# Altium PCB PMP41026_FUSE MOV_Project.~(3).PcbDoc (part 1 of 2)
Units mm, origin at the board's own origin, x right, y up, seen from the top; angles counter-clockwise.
Board outline 26.25 x 35 mm, 2 copper layers (Top Layer, Bottom Layer), stack 1.575 mm thick; 11 components, 9 nets, 22 pads, 48 vias.
Unrouted connection lines stored in the file: 16.
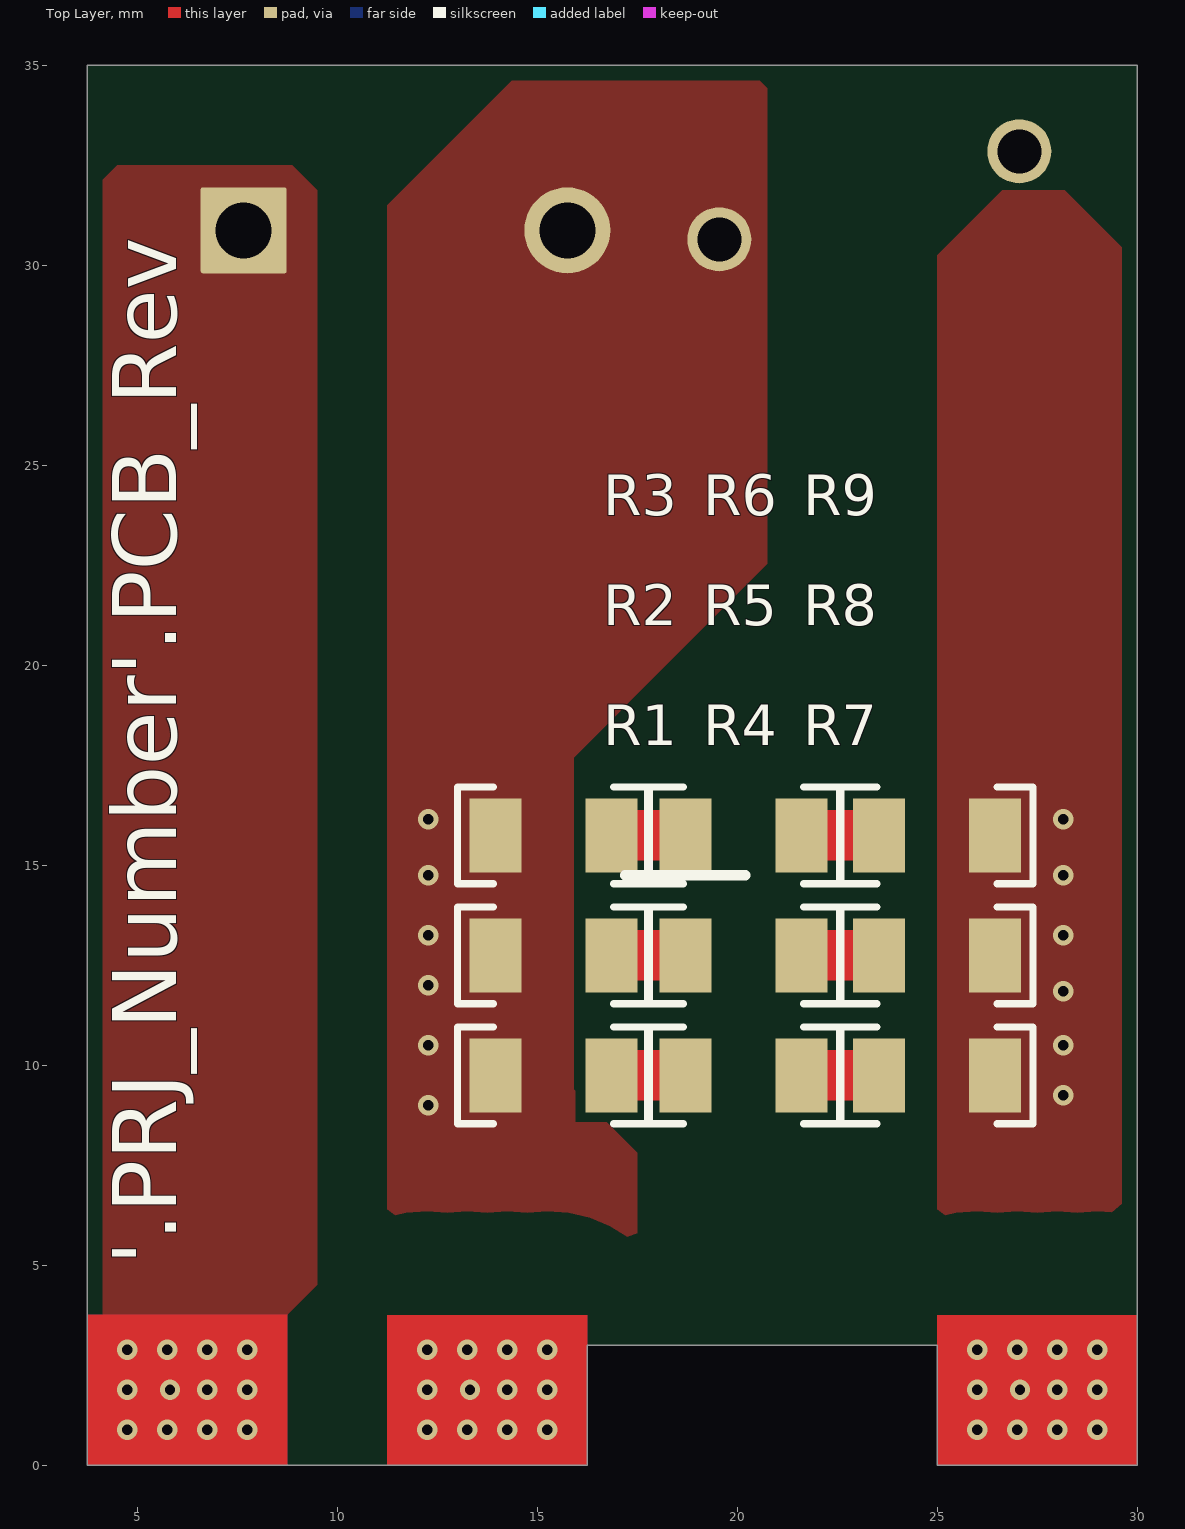
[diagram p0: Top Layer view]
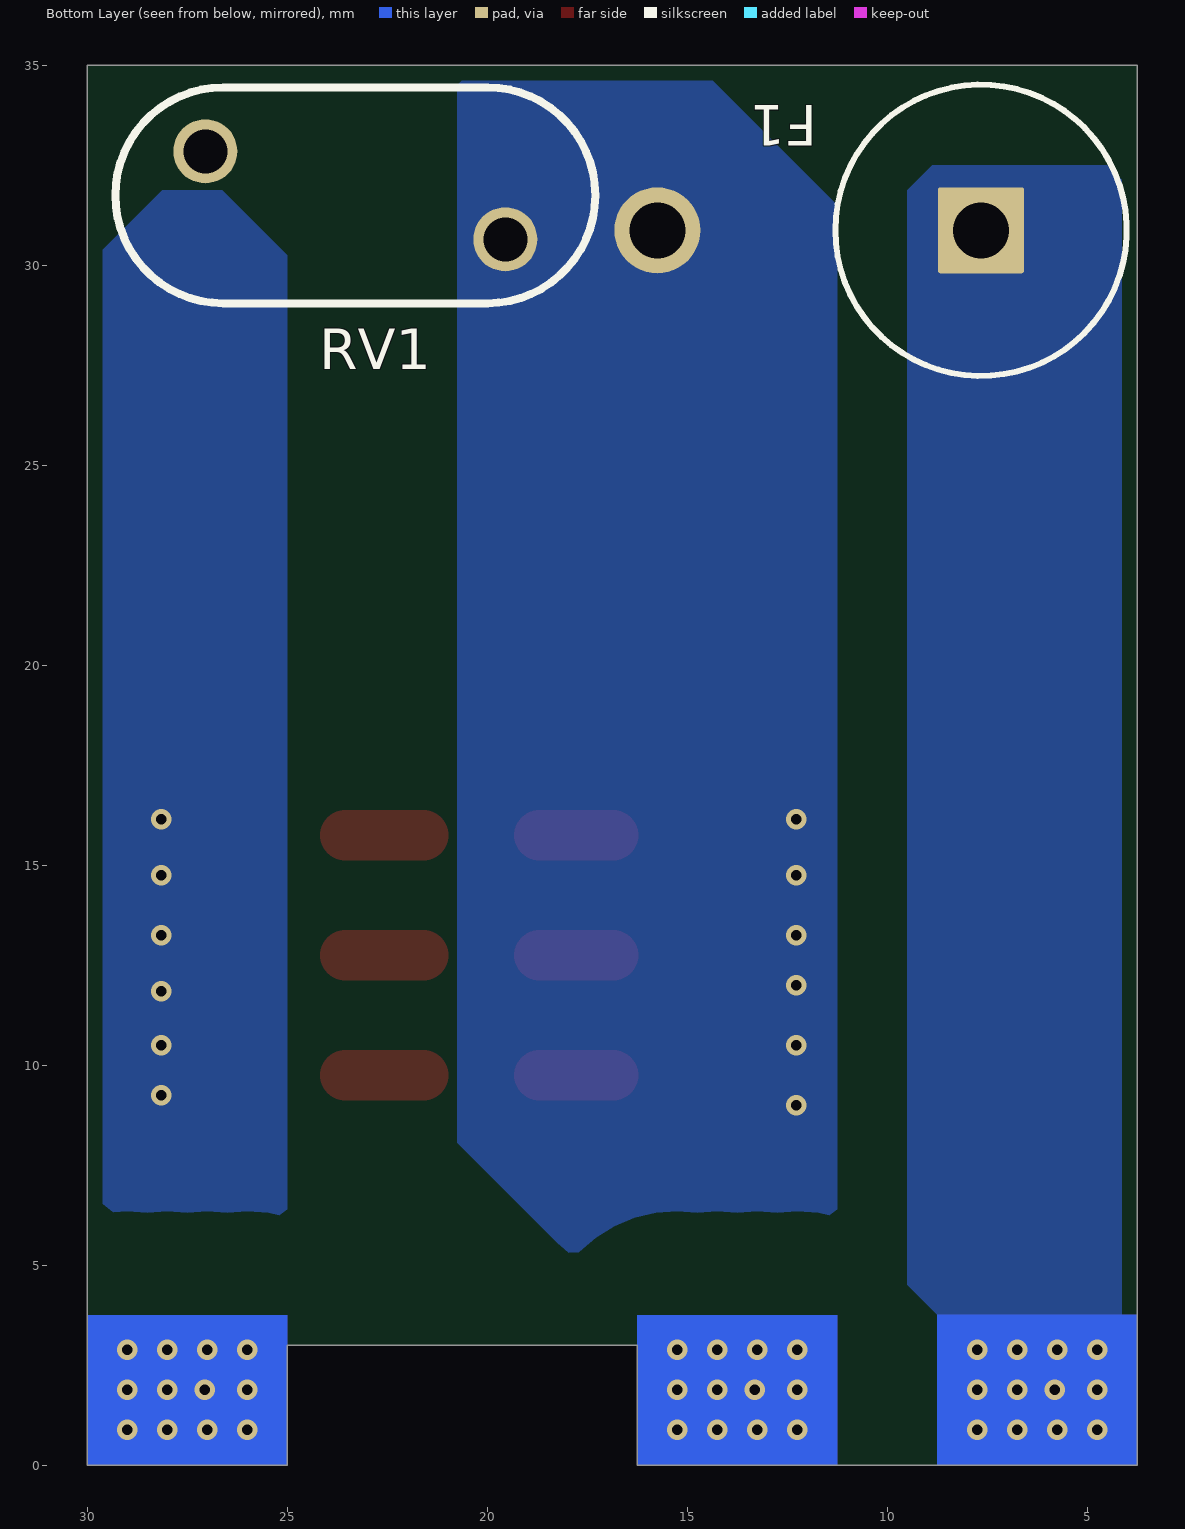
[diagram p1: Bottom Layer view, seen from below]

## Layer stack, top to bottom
Top Solder: solder mask 0.0102, Solder Resist, Dk 3.5
Top Layer: signal copper 0.0356
Dielectric1: core 1.5037, FR-4 High Tg, Dk 4.8
Bottom Layer: signal copper 0.0356
Bottom Solder: solder mask 0.0102, Solder Resist, Dk 3.5

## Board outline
3.75,0 3.75,35 30,35 30,0 25,0 25,3 16.25,3 16.25,0 11.25,0 8.75,0

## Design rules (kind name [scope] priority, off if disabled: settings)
AcuteAngle [All] p1: minimum=4.50000000000000E+0001 checktracksonly=FALSE
AssemblyTestPointUsage [All] p1: valid=2
BoardOutlineClearance BoardOutlineClearance_MountingHoles [OnCopper and InComponentClass('Mounting Holes')] p1: gap=1.016 ignorepadtopadclearanceinfootprint=FALSE
BoardOutlineClearance BoardOutlineClearance_Poly [OnCopper and IsPoly] p2: gap=0.381 ignorepadtopadclearanceinfootprint=FALSE
BoardOutlineClearance [OnCopper and Not InComponentClass('Logo') and not InComponentClass('FiducialMark') and not InRegion(1000,500,4000,800) and not InPoly] p3: gap=0.203 ignorepadtopadclearanceinfootprint=FALSE
Clearance Clearance_3 [InNetClass('L') vs Not InNetClass('L')] p1: gap=0.254 ignorepadtopadclearanceinfootprint=FALSE except(0: Arc-Hole Track-Hole SMDPad-Hole THPad-Hole Via-Hole Fill-Hole Poly-Hole Region-Hole Text-Hole)
Clearance Clearance_2 [InNetClass('N') vs InNetClass('L')] p2: gap=3.2 ignorepadtopadclearanceinfootprint=FALSE
Clearance Clearance_1 [InNetClass('N') vs Not InNetClass('N')] p3: gap=1.016 ignorepadtopadclearanceinfootprint=TRUE
Clearance Clearance_Keepouts [((IsTrack Or IsArc) And Not InPoly) And IsFree and IsKeepOut vs ((IsTrack Or IsArc) And Not InPoly) And IsFree and IsKeepOut] p4: gap=0 ignorepadtopadclearanceinfootprint=FALSE
Clearance Clearance_Poly [InPolygon] p5: gap=0.05 ignorepadtopadclearanceinfootprint=FALSE
Clearance Clearance_FiducialMark [IsKeepOut and InComponentClass('FiducialMark') vs IsPad and InComponentClass('FiducialMark')] p6: gap=0 ignorepadtopadclearanceinfootprint=FALSE
Clearance [All] p7: gap=0.05 ignorepadtopadclearanceinfootprint=TRUE
ComponentClearance ComponentClearance_MountingHoles_FiducialMarks [InComponentClass('Mounting Holes') vs InComponentClass('FiducialMark')] p1: gap=1.27 collisioncheckmode=3 verticalgap=0.254 showdistances=FALSE
ComponentClearance ComponentClearance_Shunt [InComponentClass('Header') vs InComponentClass('Shunt')] p2: gap=0 collisioncheckmode=3 verticalgap=0 showdistances=FALSE
ComponentClearance ComponentClearance_Logo [InComponentClass('Logo')] p3: gap=0.254 collisioncheckmode=3 verticalgap=0.254 showdistances=FALSE
ComponentClearance ComponentClearance_ScrewToNut [(HasFootprint('NY PMS 440 0025 PH')) vs (HasFootprint('Keystone_1902C'))] p4: gap=0.127 collisioncheckmode=3 verticalgap=0.254 showdistances=FALSE
ComponentClearance ComponentClearance_MountingHoles [InComponentClass('Mounting Holes')] p5: gap=1.27 collisioncheckmode=3 verticalgap=2540 showdistances=FALSE
ComponentClearance ComponentClearance_SmallPassives [HasFootprint('0201*') or HasFootprint('0402*') or HasFootprint('0508') or HasFootprint('0603*') or HasFootprint('0612') or HasFootprint('0805*') or HasFootprint('0815*') or HasFootprint('0830*') or HasFootprint('1206*') or HasFootprint('1210*') or HasFootprint('1808*') or HasFootprint('1812*') or HasFootprint('1825*') or HasFootprint('2010*') or HasFootprint('2220*') or HasFootprint('2225*') or HasFootprint('2512*') or HasFootprint('2728*') or HasFootprint('3518*') vs HasFootprint('0201*') or HasFootprint('0402*') or HasFootprint('0508') or HasFootprint('0603*') or HasFootprint('0612') or HasFootprint('0805*') or HasFootprint('0815*') or HasFootprint('0830*') or HasFootprint('1206*') or HasFootprint('1210*') or HasFootprint('1808*') or HasFootprint('1812*') or HasFootprint('1825*') or HasFootprint('2010*') or HasFootprint('2220*') or HasFootprint('2225*') or HasFootprint('2512*') or HasFootprint('2728*') or HasFootprint('3518*')] p6: gap=0.38 collisioncheckmode=3 verticalgap=0.254 showdistances=FALSE
ComponentClearance ComponentClearance_THtoSMT [IsThruComponent vs IsSMTComponent] p7: gap=0.254 collisioncheckmode=3 verticalgap=0.254 showdistances=FALSE
ComponentClearance ComponentClearance_THtoTH [IsThruComponent vs IsThruComponent] p8: gap=0.254 collisioncheckmode=3 verticalgap=0.254 showdistances=FALSE
ComponentClearance [All] p9: gap=0.254 collisioncheckmode=3 verticalgap=0.254 showdistances=FALSE
DiffPairsRouting [All] p1: maxlimit=2.54 minlimit=0.254 mostfreqgap=0.254 toplayer_minwidth=0.381 toplayer_maxwidth=0.381 toplayer_prefwidth=0.381 bottomlayer_minwidth=0.381 bottomlayer_maxwidth=0.381 bottomlayer_prefwidth=0.381 maxuncoupledlength=25.4
FabricationTestPointUsage TestPointUsage [All] p1: valid=2 allowmultiple=FALSE
FabricationTestpoint Testpoint [All] p1: side=3 testpointundercomponent=TRUE minsize=1.016 maxsize=2.54 preferedsize=1.524 minholesize=0 maxholesize=1.016 preferedholesize=0.813 testpointgrid=0.025 allowsidetop=TRUE allowsidebottom=TRUE usegrid=TRUE gridtolerance=0
FanoutControl Fanout_LCC [IsLCC] p1: bgadir=Out bgaviamode=Centered fanoutstyle=Auto fanoutdirection=Alternating viagrid=0.025 // Fanout_LCC (Default Rule)
FanoutControl Fanout_BGA [IsBGA] p2: bgadir=Out bgaviamode=Centered fanoutstyle=Auto fanoutdirection=Alternating viagrid=0.025 // Fanout_BGA (Default Rule)
FanoutControl Fanout_Default [All] p4: bgadir=Out bgaviamode=Centered fanoutstyle=Auto fanoutdirection=Alternating viagrid=0.025 // Fanout_Default (Default Rule)
FanoutControl Fanout_Small [(CompPinCount < 5)] p5: bgadir=Out bgaviamode=Centered fanoutstyle=Auto fanoutdirection=OutThenIn viagrid=0.025 // Fanout_Small (Default Rule)
Height [All] p1: minheight=0 maxheight=38.1 prefheight=12.7
HoleSize [All] p1: absolutevalues=TRUE maxlimit=12.7 minlimit=0.2 maxpercent=80.000 minpercent=20.000
HoleToHoleClearance [All] p1: gap=0 allowstackedmicrovias=TRUE
MinimumAnnularRing MinimumAnnularRing_ThermalPadVias [IsVia and InAnyComponent] p1: minimumring=0.15
MinimumAnnularRing [All] p2: minimumring=0.127
MinimumSolderMaskSliver MinimumSolderMaskSliver_Logo [InComponentClass('Logo') vs InComponentClass('Logo')] p1: minsoldermaskwidth=0.018
MinimumSolderMaskSliver [All] p2: minsoldermaskwidth=0.1
PlaneConnect [All] p1: planeconnectstyle=Relief reliefexpansion=0.254 reliefentries=4 reliefconductorwidth=0.254 reliefairgap=0.254
PolygonConnect PolygonConnect_59 [All vs IsNamedPolygon('PGND') Or  IsNamedPolygon('C102_1') Or  IsNamedPolygon('PGND') Or  IsNamedPolygon('F150_2') Or  IsNamedPolygon('C102_1') Or  IsNamedPolygon('F150_1') Or  IsNamedPolygon('C105_2') Or  IsNamedPolygon('ZCD') Or  IsNamedPolygon('C102_1') Or  IsNamedPolygon('C102_1') Or  IsNamedPolygon('PGND') Or  IsNamedPolygon('PGND') Or  IsNamedPolygon('Line') Or  IsNamedPolygon('F150_1') Or  IsNamedPolygon('ZCD') Or  IsNamedPolygon('Line') Or  IsNamedPolygon('Neutral') Or  IsNamedPolygon('F150_2') Or  IsNamedPolygon('Line') Or  IsNamedPolygon('Neutral') Or  IsNamedPolygon('F150_1') Or  IsNamedPolygon('PGND') Or  IsNamedPolygon('SWNODE') Or  IsNamedPolygon('SWNODE') Or  IsNamedPolygon('SWNODE') Or  IsNamedPolygon('PGND') Or  IsNamedPolygon('Line') Or  IsNamedPolygon('Vbulk1') Or  IsNamedPolygon('C105_2') Or  IsNamedPolygon('PGND') Or  IsNamedPolygon('C105_2') Or  IsNamedPolygon('PGND') Or  IsNamedPolygon('C105_1') Or  IsNamedPolygon('PGND') Or  IsNamedPolygon('Vbulk') Or  IsNamedPolygon('Vbulk') Or  IsNamedPolygon('F150_1') Or  IsNamedPolygon('Vbulk') Or  IsNamedPolygon('PGND') Or  IsNamedPolygon('C105_1') Or  IsNamedPolygon('Neutral') Or  IsNamedPolygon('Neutral') Or  IsNamedPolygon('SWNODE') Or  IsNamedPolygon('C102_1') Or  IsNamedPolygon('F150_2') Or  IsNamedPolygon('C105_1') Or  IsNamedPolygon('Line') Or  IsNamedPolygon('F150_2') Or  IsNamedPolygon('F150_2') Or  IsNamedPolygon('F150_1') Or  IsNamedPolygon('C105_1') Or  IsNamedPolygon('Vbulk1') Or  IsNamedPolygon('PGND') Or  IsNamedPolygon('C105_2') Or  IsNamedPolygon('F150_1') Or  IsNamedPolygon('C105_1') Or  IsNamedPolygon('F150_2') Or  IsNamedPolygon('C102_1') Or  IsNamedPolygon('PGND') Or  IsNamedPolygon('VBB') Or  IsNamedPolygon('12Vp') Or  IsNamedPolygon('J102_1') Or  IsNamedPolygon('J102_1') Or  IsNamedPolygon('Neutral') Or  IsNamedPolygon('Neutral') Or  IsNamedPolygon('PGND') Or  IsNamedPolygon('VBB') Or  IsNamedPolygon('Vbulk') Or  IsNamedPolygon('VBB') Or  IsNamedPolygon('C105_2') Or  IsNamedPolygon('ZCD') Or  IsNamedPolygon('C105_2') Or  IsNamedPolygon('ZCD') Or  IsNamedPolygon('Vbulk') Or  IsNamedPolygon('ZCD') Or  IsNamedPolygon('5Vp') Or  IsNamedPolygon('J102_1') Or  IsNamedPolygon('SWNODE') Or  IsNamedPolygon('PGND') Or  IsNamedPolygon('ZCD') Or  IsNamedPolygon('D106_1') Or  IsNamedPolygon('VBB') Or  IsNamedPolygon('J102_1') Or  IsNamedPolygon('J102_1') Or  IsNamedPolygon('PGND') Or  IsNamedPolygon('VBB') Or  IsNamedPolygon('D106_1') Or  IsNamedPolygon('PGND') Or  IsNamedPolygon('SWNODE') Or  IsNamedPolygon('ZCD') Or  IsNamedPolygon('PGND') Or  IsNamedPolygon('Vbulk1') Or  IsNamedPolygon('ZCD') Or  IsNamedPolygon('Line') Or  IsNamedPolygon('Vbulk') Or  IsNamedPolygon('PGND') Or  IsNamedPolygon('PGND') Or  IsNamedPolygon('VBB') Or  IsNamedPolygon('PGND') Or  IsNamedPolygon('C105_1') Or  IsNamedPolygon('VBB') Or  IsNamedPolygon('ZCD') Or  IsNamedPolygon('Neutral') Or  IsNamedPolygon('ZCD') Or  IsNamedPolygon('PE') Or  IsNamedPolygon('J102_1') Or  IsNamedPolygon('Vbulk') Or  IsNamedPolygon('Vbulk1')] p1: connectstyle=Direct reliefconductorwidth=0.254 reliefentries=4 polygonreliefangle="90 Angle" airgapwidth=0.254
PolygonConnect PolygonConnect_58 [All vs IsNamedPolygon('C105_1') Or  IsNamedPolygon('12Vp') Or  IsNamedPolygon('Neutral') Or  IsNamedPolygon('C105_2') Or  IsNamedPolygon('ZCD') Or  IsNamedPolygon('C105_1') Or  IsNamedPolygon('VBB') Or  IsNamedPolygon('PGND') Or  IsNamedPolygon('F150_2') Or  IsNamedPolygon('SWNODE') Or  IsNamedPolygon('PGND') Or  IsNamedPolygon('PGND') Or  IsNamedPolygon('J102_1') Or  IsNamedPolygon('D106_1') Or  IsNamedPolygon('PGND') Or  IsNamedPolygon('C105_2') Or  IsNamedPolygon('SWNODE') Or  IsNamedPolygon('Vbulk') Or  IsNamedPolygon('PGND') Or  IsNamedPolygon('PGND') Or  IsNamedPolygon('PGND') Or  IsNamedPolygon('PGND') Or  IsNamedPolygon('Vbulk') Or  IsNamedPolygon('PGND') Or  IsNamedPolygon('PGND') Or  IsNamedPolygon('D106_1') Or  IsNamedPolygon('Neutral') Or  IsNamedPolygon('PGND') Or  IsNamedPolygon('C105_2') Or  IsNamedPolygon('Vbulk') Or  IsNamedPolygon('SWNODE') Or  IsNamedPolygon('VBB') Or  IsNamedPolygon('J102_1') Or  IsNamedPolygon('VBB') Or  IsNamedPolygon('PGND') Or  IsNamedPolygon('5Vp') Or  IsNamedPolygon('SWNODE') Or  IsNamedPolygon('C105_1') Or  IsNamedPolygon('VBB') Or  IsNamedPolygon('SWNODE') Or  IsNamedPolygon('ZCD') Or  IsNamedPolygon('Vbulk') Or  IsNamedPolygon('Line') Or  IsNamedPolygon('Vbulk1') Or  IsNamedPolygon('PGND') Or  IsNamedPolygon('ZCD') Or  IsNamedPolygon('VBB') Or  IsNamedPolygon('PGND') Or  IsNamedPolygon('ZCD') Or  IsNamedPolygon('Vbulk1') Or  IsNamedPolygon('Neutral') Or  IsNamedPolygon('F150_2') Or  IsNamedPolygon('F150_2') Or  IsNamedPolygon('PGND') Or  IsNamedPolygon('Neutral') Or  IsNamedPolygon('C102_1') Or  IsNamedPolygon('C105_1') Or  IsNamedPolygon('Line') Or  IsNamedPolygon('J102_1') Or  IsNamedPolygon('Neutral') Or  IsNamedPolygon('Neutral') Or  IsNamedPolygon('SWNODE') Or  IsNamedPolygon('ZCD') Or  IsNamedPolygon('J102_1') Or  IsNamedPolygon('J102_1') Or  IsNamedPolygon('PGND') Or  IsNamedPolygon('ZCD') Or  IsNamedPolygon('Vbulk') Or  IsNamedPolygon('Line') Or  IsNamedPolygon('VBB') Or  IsNamedPolygon('Vbulk') Or  IsNamedPolygon('VBB') Or  IsNamedPolygon('Line') Or  IsNamedPolygon('C105_1') Or  IsNamedPolygon('ZCD') Or  IsNamedPolygon('C105_2') Or  IsNamedPolygon('Line') Or  IsNamedPolygon('C105_2') Or  IsNamedPolygon('PGND') Or  IsNamedPolygon('PE') Or  IsNamedPolygon('Neutral') Or  IsNamedPolygon('F150_2') Or  IsNamedPolygon('ZCD') Or  IsNamedPolygon('F150_2') Or  IsNamedPolygon('F150_2') Or  IsNamedPolygon('ZCD') Or  IsNamedPolygon('PGND') Or  IsNamedPolygon('PGND') Or  IsNamedPolygon('Vbulk1') Or  IsNamedPolygon('Line') Or  IsNamedPolygon('ZCD') Or  IsNamedPolygon('C105_1') Or  IsNamedPolygon('J102_1') Or  IsNamedPolygon('Vbulk1') Or  IsNamedPolygon('Vbulk') Or  IsNamedPolygon('C105_2') Or  IsNamedPolygon('PGND')] p2: connectstyle=Direct reliefconductorwidth=0.254 reliefentries=4 polygonreliefangle="90 Angle" airgapwidth=0.254
PolygonConnect PolygonConnect_57 [All vs IsNamedPolygon('PGND') Or  IsNamedPolygon('C105_2') Or  IsNamedPolygon('VBB') Or  IsNamedPolygon('5Vp') Or  IsNamedPolygon('ZCD') Or  IsNamedPolygon('J102_1') Or  IsNamedPolygon('PGND') Or  IsNamedPolygon('PGND') Or  IsNamedPolygon('PGND') Or  IsNamedPolygon('PE') Or  IsNamedPolygon('VBB') Or  IsNamedPolygon('VBB') Or  IsNamedPolygon('ZCD') Or  IsNamedPolygon('ZCD') Or  IsNamedPolygon('Line') Or  IsNamedPolygon('PGND') Or  IsNamedPolygon('C102_1') Or  IsNamedPolygon('VBB') Or  IsNamedPolygon('J102_1') Or  IsNamedPolygon('Vbulk') Or  IsNamedPolygon('PGND') Or  IsNamedPolygon('Neutral') Or  IsNamedPolygon('Vbulk') Or  IsNamedPolygon('ZCD') Or  IsNamedPolygon('J102_1') Or  IsNamedPolygon('PGND') Or  IsNamedPolygon('ZCD') Or  IsNamedPolygon('J102_1') Or  IsNamedPolygon('VBB') Or  IsNamedPolygon('Neutral') Or  IsNamedPolygon('PGND') Or  IsNamedPolygon('PGND') Or  IsNamedPolygon('12Vp') Or  IsNamedPolygon('Vbulk') Or  IsNamedPolygon('PGND') Or  IsNamedPolygon('Vbulk') Or  IsNamedPolygon('J102_1') Or  IsNamedPolygon('PGND') Or  IsNamedPolygon('D106_1') Or  IsNamedPolygon('PGND') Or  IsNamedPolygon('Vbulk1') Or  IsNamedPolygon('PGND') Or  IsNamedPolygon('C105_2') Or  IsNamedPolygon('Vbulk') Or  IsNamedPolygon('Neutral') Or  IsNamedPolygon('Vbulk1') Or  IsNamedPolygon('PGND') Or  IsNamedPolygon('PGND') Or  IsNamedPolygon('J102_1') Or  IsNamedPolygon('SWNODE') Or  IsNamedPolygon('Vbulk1') Or  IsNamedPolygon('C105_2') Or  IsNamedPolygon('VBB') Or  IsNamedPolygon('VBB') Or  IsNamedPolygon('ZCD') Or  IsNamedPolygon('SWNODE') Or  IsNamedPolygon('Vbulk') Or  IsNamedPolygon('PGND') Or  IsNamedPolygon('Vbulk') Or  IsNamedPolygon('C105_1') Or  IsNamedPolygon('PGND') Or  IsNamedPolygon('PGND') Or  IsNamedPolygon('ZCD') Or  IsNamedPolygon('C105_2') Or  IsNamedPolygon('D106_1') Or  IsNamedPolygon('PGND') Or  IsNamedPolygon('C105_2') Or  IsNamedPolygon('C105_2') Or  IsNamedPolygon('ZCD') Or  IsNamedPolygon('PGND')] p3: connectstyle=Direct reliefconductorwidth=0.254 reliefentries=4 polygonreliefangle="90 Angle" airgapwidth=0.254
PolygonConnect PolygonConnect_56 [All vs IsNamedPolygon('PGND') Or  IsNamedPolygon('C105_2') Or  IsNamedPolygon('VBB') Or  IsNamedPolygon('5Vp') Or  IsNamedPolygon('ZCD') Or  IsNamedPolygon('J102_1') Or  IsNamedPolygon('PGND') Or  IsNamedPolygon('PGND') Or  IsNamedPolygon('PGND') Or  IsNamedPolygon('PE') Or  IsNamedPolygon('VBB') Or  IsNamedPolygon('VBB') Or  IsNamedPolygon('ZCD') Or  IsNamedPolygon('ZCD') Or  IsNamedPolygon('Line') Or  IsNamedPolygon('PGND') Or  IsNamedPolygon('C102_1') Or  IsNamedPolygon('VBB') Or  IsNamedPolygon('J102_1') Or  IsNamedPolygon('Vbulk') Or  IsNamedPolygon('PGND') Or  IsNamedPolygon('Neutral') Or  IsNamedPolygon('Vbulk') Or  IsNamedPolygon('ZCD') Or  IsNamedPolygon('J102_1') Or  IsNamedPolygon('PGND') Or  IsNamedPolygon('ZCD') Or  IsNamedPolygon('J102_1') Or  IsNamedPolygon('VBB') Or  IsNamedPolygon('Neutral') Or  IsNamedPolygon('PGND') Or  IsNamedPolygon('PGND') Or  IsNamedPolygon('12Vp') Or  IsNamedPolygon('Vbulk') Or  IsNamedPolygon('PGND') Or  IsNamedPolygon('Vbulk') Or  IsNamedPolygon('J102_1') Or  IsNamedPolygon('PGND') Or  IsNamedPolygon('D106_1') Or  IsNamedPolygon('PGND') Or  IsNamedPolygon('Vbulk1') Or  IsNamedPolygon('PGND') Or  IsNamedPolygon('C105_2') Or  IsNamedPolygon('Vbulk') Or  IsNamedPolygon('Neutral') Or  IsNamedPolygon('Vbulk1') Or  IsNamedPolygon('PGND') Or  IsNamedPolygon('PGND') Or  IsNamedPolygon('J102_1') Or  IsNamedPolygon('SWNODE') Or  IsNamedPolygon('Vbulk1') Or  IsNamedPolygon('C105_2') Or  IsNamedPolygon('VBB') Or  IsNamedPolygon('VBB') Or  IsNamedPolygon('ZCD') Or  IsNamedPolygon('SWNODE') Or  IsNamedPolygon('Vbulk') Or  IsNamedPolygon('PGND') Or  IsNamedPolygon('Vbulk') Or  IsNamedPolygon('C105_1') Or  IsNamedPolygon('PGND') Or  IsNamedPolygon('PGND') Or  IsNamedPolygon('ZCD') Or  IsNamedPolygon('C105_2') Or  IsNamedPolygon('D106_1') Or  IsNamedPolygon('PGND') Or  IsNamedPolygon('C105_2') Or  IsNamedPolygon('C105_2') Or  IsNamedPolygon('ZCD') Or  IsNamedPolygon('PGND')] p4: thpad.connectstyle=Direct thpad.reliefconductorwidth=0.254 thpad.reliefentries=4 thpad.polygonreliefangle="90 Angle" thpad.airgapwidth=0.254 smdpad.connectstyle=Relief smdpad.reliefconductorwidth=0.254 smdpad.reliefentries=4 smdpad.polygonreliefangle="90 Angle" smdpad.airgapwidth=0.254 via.connectstyle=Relief via.reliefconductorwidth=0.254 via.reliefentries=4 via.polygonreliefangle="90 Angle" via.airgapwidth=0.254
PolygonConnect PolygonConnect_55 [All vs IsNamedPolygon('SWNODE') Or  IsNamedPolygon('ZCD') Or  IsNamedPolygon('PGND') Or  IsNamedPolygon('PGND') Or  IsNamedPolygon('PGND') Or  IsNamedPolygon('PGND') Or  IsNamedPolygon('PGND') Or  IsNamedPolygon('PGND') Or  IsNamedPolygon('Vbulk') Or  IsNamedPolygon('D106_1') Or  IsNamedPolygon('Vbulk') Or  IsNamedPolygon('D106_1') Or  IsNamedPolygon('VBB') Or  IsNamedPolygon('PGND') Or  IsNamedPolygon('PGND') Or  IsNamedPolygon('Vbulk') Or  IsNamedPolygon('VBB') Or  IsNamedPolygon('ZCD') Or  IsNamedPolygon('Vbulk') Or  IsNamedPolygon('ZCD') Or  IsNamedPolygon('VBB') Or  IsNamedPolygon('VBB') Or  IsNamedPolygon('VBB') Or  IsNamedPolygon('VBB') Or  IsNamedPolygon('VBB') Or  IsNamedPolygon('ZCD') Or  IsNamedPolygon('C102_1') Or  IsNamedPolygon('12Vp') Or  IsNamedPolygon('C105_1') Or  IsNamedPolygon('PGND') Or  IsNamedPolygon('SWNODE') Or  IsNamedPolygon('Vbulk') Or  IsNamedPolygon('Vbulk1') Or  IsNamedPolygon('Vbulk1') Or  IsNamedPolygon('Neutral') Or  IsNamedPolygon('ZCD') Or  IsNamedPolygon('Neutral') Or  IsNamedPolygon('ZCD') Or  IsNamedPolygon('5Vp') Or  IsNamedPolygon('Neutral') Or  IsNamedPolygon('ZCD') Or  IsNamedPolygon('Line') Or  IsNamedPolygon('ZCD')] p5: connectstyle=Direct reliefconductorwidth=0.254 reliefentries=4 polygonreliefangle="90 Angle" airgapwidth=0.254
PolygonConnect PolygonConnect_54 [All vs IsNamedPolygon('12Vp') Or  IsNamedPolygon('SWNODE') Or  IsNamedPolygon('D403_2') Or  IsNamedPolygon('D403_2') Or  IsNamedPolygon('PGND') Or  IsNamedPolygon('BOTTOM_LAYER_NETC106_2_P030') Or  IsNamedPolygon('C102_1') Or  IsNamedPolygon('SGND') Or  IsNamedPolygon('TOP_LAYER_54V1_P046') Or  IsNamedPolygon('TOP_LAYER_54V2_P048') Or  IsNamedPolygon('TOP_LAYER_54V2_P048') Or  IsNamedPolygon('C108_1') Or  IsNamedPolygon('C108_1') Or  IsNamedPolygon('C108_1') Or  IsNamedPolygon('C108_1') Or  IsNamedPolygon('C108_1') Or  IsNamedPolygon('C108_1') Or  IsNamedPolygon('PGND') Or  IsNamedPolygon('ZCD') Or  IsNamedPolygon('Line') Or  IsNamedPolygon('5Vp') Or  IsNamedPolygon('12Vp') Or  IsNamedPolygon('T200_4') Or  IsNamedPolygon('T200_6') Or  IsNamedPolygon('SWNODE3') Or  IsNamedPolygon('T200_4') Or  IsNamedPolygon('T200_6') Or  IsNamedPolygon('SWNODE4') Or  IsNamedPolygon('VSR') Or  IsNamedPolygon('TOP_LAYER_IOUT_SNS_P092') Or  IsNamedPolygon('SIGNAL_LAYER_2_VBB_P094') Or  IsNamedPolygon('Vbulk1') Or  IsNamedPolygon('TOP_LAYER_VBULK_P104') Or  IsNamedPolygon('SIGNAL_LAYER_1_VBULK1_P106') Or  IsNamedPolygon('Line') Or  IsNamedPolygon('Line') Or  IsNamedPolygon('D404_2') Or  IsNamedPolygon('Vbulk') Or  IsNamedPolygon('D400_2') Or  IsNamedPolygon('SGND') Or  IsNamedPolygon('PGND') Or  IsNamedPolygon('TOP_LAYER_12VS_P126') Or  IsNamedPolygon('LEG3_HS_DRV') Or  IsNamedPolygon('LEG4_LS_DRV') Or  IsNamedPolygon('LEG4_HS_DRV') Or  IsNamedPolygon('SWNODE4') Or  IsNamedPolygon('SWNODE3') Or  IsNamedPolygon('T200_6') Or  IsNamedPolygon('T200_4') Or  IsNamedPolygon('VBB') Or  IsNamedPolygon('5Vs') Or  IsNamedPolygon('SGND') Or  IsNamedPolygon('Iout_SNS') Or  IsNamedPolygon('SGND') Or  IsNamedPolygon('SWNODE3') Or  IsNamedPolygon('SWNODE3') Or  IsNamedPolygon('SWNODE3') Or  IsNamedPolygon('SWNODE3') Or  IsNamedPolygon('SGND') Or  IsNamedPolygon('SGND') Or  IsNamedPolygon('SGND') Or  IsNamedPolygon('SWNODE4') Or  IsNamedPolygon('SWNODE4') Or  IsNamedPolygon('SWNODE4') Or  IsNamedPolygon('VSR') Or  IsNamedPolygon('SWNODE3') Or  IsNamedPolygon('SGND') Or  IsNamedPolygon('SGND') Or  IsNamedPolygon('SGND') Or  IsNamedPolygon('SGND') Or  IsNamedPolygon('SGND') Or  IsNamedPolygon('SGND') Or  IsNamedPolygon('54V1') Or  IsNamedPolygon('SGND') Or  IsNamedPolygon('VSR') Or  IsNamedPolygon('C102_1') Or  IsNamedPolygon('C102_1') Or  IsNamedPolygon('C102_1') Or  IsNamedPolygon('C102_1') Or  IsNamedPolygon('C102_1') Or  IsNamedPolygon('ZCD') Or  IsNamedPolygon('PGND') Or  IsNamedPolygon('PGND') Or  IsNamedPolygon('Vbulk1') Or  IsNamedPolygon('Vbulk') Or  IsNamedPolygon('Vbulk1') Or  IsNamedPolygon('Vbulk1') Or  IsNamedPolygon('ZCD') Or  IsNamedPolygon('Neutral') Or  IsNamedPolygon('Neutral') Or  IsNamedPolygon('C106_2') Or  IsNamedPolygon('C106_2') Or  IsNamedPolygon('C106_2') Or  IsNamedPolygon('SWNODE') Or  IsNamedPolygon('Vbulk1') Or  IsNamedPolygon('Earth1') Or  IsNamedPolygon('Earth1') Or  IsNamedPolygon('Earth1') Or  IsNamedPolygon('Earth1') Or  IsNamedPolygon('Earth1') Or  IsNamedPolygon('Earth1') Or  IsNamedPolygon('ZCD') Or  IsNamedPolygon('VBB') Or  IsNamedPolygon('PGND') Or  IsNamedPolygon('D106_1') Or  IsNamedPolygon('PGND') Or  IsNamedPolygon('PGND') Or  IsNamedPolygon('D106_1') Or  IsNamedPolygon('Vbulk') Or  IsNamedPolygon('D106_1') Or  IsNamedPolygon('PGND') Or  IsNamedPolygon('VBB') Or  IsNamedPolygon('VBB') Or  IsNamedPolygon('PGND') Or  IsNamedPolygon('PGND') Or  IsNamedPolygon('PGND') Or  IsNamedPolygon('PGND') Or  IsNamedPolygon('PGND') Or  IsNamedPolygon('ZCD') Or  IsNamedPolygon('ZCD') Or  IsNamedPolygon('C412_2') Or  IsNamedPolygon('VBB') Or  IsNamedPolygon('PGND') Or  IsNamedPolygon('PGND') Or  IsNamedPolygon('PGND') Or  IsNamedPolygon('PGND') Or  IsNamedPolygon('PGND') Or  IsNamedPolygon('PGND') Or  IsNamedPolygon('PGND') Or  IsNamedPolygon('Vbulk') Or  IsNamedPolygon('D404_2') Or  IsNamedPolygon('PGND') Or  IsNamedPolygon('Iout_SNS') Or  IsNamedPolygon('54V2') Or  IsNamedPolygon('54V2') Or  IsNamedPolygon('54V2') Or  IsNamedPolygon('54V2') Or  IsNamedPolygon('VSR') Or  IsNamedPolygon('VSR') Or  IsNamedPolygon('Iout_SNS') Or  IsNamedPolygon('SGND') Or  IsNamedPolygon('SGND') Or  IsNamedPolygon('BOTTOM_LAYER_54V1_P154') Or  IsNamedPolygon('ZCD') Or  IsNamedPolygon('PGND')] p6: connectstyle=Direct reliefconductorwidth=0.254 reliefentries=4 polygonreliefangle="90 Angle" airgapwidth=0.254
PolygonConnect PolygonConnect_53 [All vs IsNamedPolygon('BOTTOM_LAYER_54V1_P350')] p7: connectstyle=Direct reliefconductorwidth=0.254 reliefentries=4 polygonreliefangle="90 Angle" airgapwidth=0.254
PolygonConnect PolygonConnect_52 [All vs IsNamedPolygon('TOP_LAYER_54V1_P046')] p8: connectstyle=Direct reliefconductorwidth=0.254 reliefentries=4 polygonreliefangle="90 Angle" airgapwidth=0.254
PolygonConnect PolygonConnect_51 [All vs IsNamedPolygon('SIGNAL_LAYER_1_VBULK1_P106')] p9: connectstyle=Direct reliefconductorwidth=0.254 reliefentries=4 polygonreliefangle="90 Angle" airgapwidth=0.254
PolygonConnect PolygonConnect_50 [All vs IsNamedPolygon('BOTTOM_LAYER_54V1_P128')] p10: connectstyle=Direct reliefconductorwidth=0.254 reliefentries=4 polygonreliefangle="90 Angle" airgapwidth=0.254
PolygonConnect PolygonConnect_49 [All vs IsNamedPolygon('BOTTOM_LAYER_54V1_P128')] p11: connectstyle=Direct reliefconductorwidth=0.254 reliefentries=4 polygonreliefangle="90 Angle" airgapwidth=0.254
PolygonConnect PolygonConnect_48 [All vs IsNamedPolygon('BOTTOM_LAYER_54V1_P128')] p12: connectstyle=Direct reliefconductorwidth=0.254 reliefentries=4 polygonreliefangle="90 Angle" airgapwidth=0.254
PolygonConnect PolygonConnect_47 [All vs IsNamedPolygon('BOTTOM_LAYER_54V1_P128')] p13: connectstyle=Direct reliefconductorwidth=0.254 reliefentries=4 polygonreliefangle="90 Angle" airgapwidth=0.254
PolygonConnect PolygonConnect_46 [All vs IsNamedPolygon('PGND') Or  IsNamedPolygon('T200_4') Or  IsNamedPolygon('VBB') Or  IsNamedPolygon('SWNODE3') Or  IsNamedPolygon('LEG4_LS_DRV') Or  IsNamedPolygon('Iout_SNS') Or  IsNamedPolygon('SWNODE3') Or  IsNamedPolygon('T200_6') Or  IsNamedPolygon('SGND') Or  IsNamedPolygon('SIGNAL_LAYER_1_VBULK1_P106') Or  IsNamedPolygon('LEG3_HS_DRV') Or  IsNamedPolygon('TOP_LAYER_12VS_P126') Or  IsNamedPolygon('LEG4_HS_DRV') Or  IsNamedPolygon('SWNODE3') Or  IsNamedPolygon('SGND') Or  IsNamedPolygon('BOTTOM_LAYER_54V1_P128') Or  IsNamedPolygon('SGND') Or  IsNamedPolygon('Line') Or  IsNamedPolygon('TOP_LAYER_IOUT_SNS_P092') Or  IsNamedPolygon('C108_1') Or  IsNamedPolygon('D403_2') Or  IsNamedPolygon('SWNODE') Or  IsNamedPolygon('SIGNAL_LAYER_2_VBB_P094') Or  IsNamedPolygon('Vbulk') Or  IsNamedPolygon('D404_2') Or  IsNamedPolygon('VSR') Or  IsNamedPolygon('C108_1') Or  IsNamedPolygon('C108_1') Or  IsNamedPolygon('5Vp') Or  IsNamedPolygon('C108_1') Or  IsNamedPolygon('PGND') Or  IsNamedPolygon('D400_2') Or  IsNamedPolygon('SWNODE3') Or  IsNamedPolygon('Line') Or  IsNamedPolygon('C108_1') Or  IsNamedPolygon('TOP_LAYER_VBULK_P104') Or  IsNamedPolygon('Vbulk1') Or  IsNamedPolygon('T200_6') Or  IsNamedPolygon('T200_6') Or  IsNamedPolygon('SWNODE4') Or  IsNamedPolygon('C108_1') Or  IsNamedPolygon('D403_2') Or  IsNamedPolygon('PGND') Or  IsNamedPolygon('T200_4') Or  IsNamedPolygon('Line') Or  IsNamedPolygon('5Vs') Or  IsNamedPolygon('12Vp') Or  IsNamedPolygon('C102_1') Or  IsNamedPolygon('SGND') Or  IsNamedPolygon('TOP_LAYER_54V2_P048') Or  IsNamedPolygon('TOP_LAYER_54V1_P046') Or  IsNamedPolygon('SWNODE4') Or  IsNamedPolygon('ZCD') Or  IsNamedPolygon('SWNODE3') Or  IsNamedPolygon('SWNODE3') Or  IsNamedPolygon('BOTTOM_LAYER_NETC106_2_P030') Or  IsNamedPolygon('TOP_LAYER_54V2_P048') Or  IsNamedPolygon('T200_4') Or  IsNamedPolygon('SWNODE4') Or  IsNamedPolygon('SWNODE4') Or  IsNamedPolygon('SGND') Or  IsNamedPolygon('SGND') Or  IsNamedPolygon('SGND') Or  IsNamedPolygon('SWNODE4') Or  IsNamedPolygon('VSR') Or  IsNamedPolygon('SWNODE3') Or  IsNamedPolygon('SGND') Or  IsNamedPolygon('SGND') Or  IsNamedPolygon('SGND') Or  IsNamedPolygon('SGND') Or  IsNamedPolygon('SGND') Or  IsNamedPolygon('SGND') Or  IsNamedPolygon('BOTTOM_LAYER_54V1_P128') Or  IsNamedPolygon('SGND') Or  IsNamedPolygon('VSR') Or  IsNamedPolygon('C102_1') Or  IsNamedPolygon('C102_1') Or  IsNamedPolygon('C102_1') Or  IsNamedPolygon('C102_1') Or  IsNamedPolygon('C102_1') Or  IsNamedPolygon('ZCD') Or  IsNamedPolygon('PGND') Or  IsNamedPolygon('PGND') Or  IsNamedPolygon('Vbulk1') Or  IsNamedPolygon('Vbulk') Or  IsNamedPolygon('Vbulk1') Or  IsNamedPolygon('Vbulk1') Or  IsNamedPolygon('ZCD') Or  IsNamedPolygon('Neutral') Or  IsNamedPolygon('Neutral') Or  IsNamedPolygon('C106_2') Or  IsNamedPolygon('C106_2') Or  IsNamedPolygon('C106_2') Or  IsNamedPolygon('SWNODE') Or  IsNamedPolygon('Vbulk1') Or  IsNamedPolygon('Earth1') Or  IsNamedPolygon('Earth1') Or  IsNamedPolygon('Earth1') Or  IsNamedPolygon('Earth1') Or  IsNamedPolygon('Earth1') Or  IsNamedPolygon('Earth1') Or  IsNamedPolygon('ZCD') Or  IsNamedPolygon('VBB') Or  IsNamedPolygon('PGND') Or  IsNamedPolygon('D106_1') Or  IsNamedPolygon('PGND') Or  IsNamedPolygon('PGND') Or  IsNamedPolygon('D106_1') Or  IsNamedPolygon('Vbulk') Or  IsNamedPolygon('D106_1') Or  IsNamedPolygon('PGND') Or  IsNamedPolygon('VBB') Or  IsNamedPolygon('VBB') Or  IsNamedPolygon('PGND') Or  IsNamedPolygon('PGND') Or  IsNamedPolygon('PGND') Or  IsNamedPolygon('PGND') Or  IsNamedPolygon('PGND') Or  IsNamedPolygon('ZCD') Or  IsNamedPolygon('ZCD') Or  IsNamedPolygon('C412_2') Or  IsNamedPolygon('VBB') Or  IsNamedPolygon('PGND') Or  IsNamedPolygon('PGND') Or  IsNamedPolygon('PGND') Or  IsNamedPolygon('PGND') Or  IsNamedPolygon('PGND') Or  IsNamedPolygon('PGND') Or  IsNamedPolygon('PGND') Or  IsNamedPolygon('Vbulk') Or  IsNamedPolygon('D404_2') Or  IsNamedPolygon('PGND') Or  IsNamedPolygon('Iout_SNS') Or  IsNamedPolygon('54V2')] p14: connectstyle=Direct reliefconductorwidth=0.254 reliefentries=4 polygonreliefangle="90 Angle" airgapwidth=0.254
PolygonConnect PolygonConnect_45 [All vs IsNamedPolygon('Vbulk1') Or  IsNamedPolygon('TOP_LAYER_VBULK_P104') Or  IsNamedPolygon('SIGNAL_LAYER_1_VBULK1_P106') Or  IsNamedPolygon('Iout_SNS') Or  IsNamedPolygon('SIGNAL_LAYER_2_VBB_P094') Or  IsNamedPolygon('Line') Or  IsNamedPolygon('T200_4') Or  IsNamedPolygon('ZCD') Or  IsNamedPolygon('C108_1') Or  IsNamedPolygon('PGND') Or  IsNamedPolygon('BOTTOM_LAYER_NETC106_2_P030') Or  IsNamedPolygon('5Vp') Or  IsNamedPolygon('C108_1') Or  IsNamedPolygon('Line') Or  IsNamedPolygon('C102_1') Or  IsNamedPolygon('T200_4') Or  IsNamedPolygon('12Vp') Or  IsNamedPolygon('D403_2') Or  IsNamedPolygon('T200_6') Or  IsNamedPolygon('TOP_LAYER_54V1_P046') Or  IsNamedPolygon('TOP_LAYER_54V2_P048') Or  IsNamedPolygon('C108_1') Or  IsNamedPolygon('C108_1') Or  IsNamedPolygon('SWNODE3') Or  IsNamedPolygon('TOP_LAYER_54V2_P048') Or  IsNamedPolygon('PGND') Or  IsNamedPolygon('D403_2') Or  IsNamedPolygon('C108_1') Or  IsNamedPolygon('C108_1') Or  IsNamedPolygon('T200_6') Or  IsNamedPolygon('SGND') Or  IsNamedPolygon('SWNODE') Or  IsNamedPolygon('SGND') Or  IsNamedPolygon('SWNODE3') Or  IsNamedPolygon('BOTTOM_LAYER_54V1_P128') Or  IsNamedPolygon('C102_1') Or  IsNamedPolygon('SWNODE4') Or  IsNamedPolygon('C102_1') Or  IsNamedPolygon('SGND') Or  IsNamedPolygon('C102_1') Or  IsNamedPolygon('SGND') Or  IsNamedPolygon('VSR') Or  IsNamedPolygon('SGND') Or  IsNamedPolygon('SGND') Or  IsNamedPolygon('VSR') Or  IsNamedPolygon('SGND') Or  IsNamedPolygon('SWNODE4') Or  IsNamedPolygon('SGND') Or  IsNamedPolygon('SGND') Or  IsNamedPolygon('Vbulk1') Or  IsNamedPolygon('SGND') Or  IsNamedPolygon('PGND') Or  IsNamedPolygon('SGND') Or  IsNamedPolygon('PGND') Or  IsNamedPolygon('SWNODE3') Or  IsNamedPolygon('ZCD') Or  IsNamedPolygon('VSR') Or  IsNamedPolygon('C102_1') Or  IsNamedPolygon('SWNODE4') Or  IsNamedPolygon('C102_1') Or  IsNamedPolygon('SWNODE4') Or  IsNamedPolygon('SWNODE3') Or  IsNamedPolygon('PGND') Or  IsNamedPolygon('SGND') Or  IsNamedPolygon('D400_2') Or  IsNamedPolygon('SGND') Or  IsNamedPolygon('5Vs') Or  IsNamedPolygon('VBB') Or  IsNamedPolygon('T200_4') Or  IsNamedPolygon('T200_6') Or  IsNamedPolygon('SWNODE4') Or  IsNamedPolygon('LEG4_HS_DRV') Or  IsNamedPolygon('LEG4_LS_DRV') Or  IsNamedPolygon('LEG3_HS_DRV') Or  IsNamedPolygon('BOTTOM_LAYER_54V1_P128') Or  IsNamedPolygon('TOP_LAYER_12VS_P126') Or  IsNamedPolygon('Iout_SNS') Or  IsNamedPolygon('SWNODE3') Or  IsNamedPolygon('SWNODE3') Or  IsNamedPolygon('SWNODE3') Or  IsNamedPolygon('VBB') Or  IsNamedPolygon('Line') Or  IsNamedPolygon('D404_2') Or  IsNamedPolygon('SGND') Or  IsNamedPolygon('VBB') Or  IsNamedPolygon('VBB') Or  IsNamedPolygon('PGND') Or  IsNamedPolygon('PGND') Or  IsNamedPolygon('PGND') Or  IsNamedPolygon('PGND') Or  IsNamedPolygon('PGND') Or  IsNamedPolygon('ZCD') Or  IsNamedPolygon('ZCD') Or  IsNamedPolygon('C412_2') Or  IsNamedPolygon('VBB') Or  IsNamedPolygon('PGND') Or  IsNamedPolygon('PGND') Or  IsNamedPolygon('PGND') Or  IsNamedPolygon('PGND') Or  IsNamedPolygon('PGND') Or  IsNamedPolygon('PGND') Or  IsNamedPolygon('PGND') Or  IsNamedPolygon('VBB') Or  IsNamedPolygon('D404_2') Or  IsNamedPolygon('VBB') Or  IsNamedPolygon('Vbulk1') Or  IsNamedPolygon('Vbulk1') Or  IsNamedPolygon('ZCD') Or  IsNamedPolygon('Neutral') Or  IsNamedPolygon('Neutral') Or  IsNamedPolygon('C106_2') Or  IsNamedPolygon('C106_2') Or  IsNamedPolygon('C106_2') Or  IsNamedPolygon('SWNODE') Or  IsNamedPolygon('Vbulk1') Or  IsNamedPolygon('Earth1') Or  IsNamedPolygon('Earth1') Or  IsNamedPolygon('Earth1') Or  IsNamedPolygon('Earth1') Or  IsNamedPolygon('Earth1') Or  IsNamedPolygon('Earth1') Or  IsNamedPolygon('ZCD') Or  IsNamedPolygon('VBB') Or  IsNamedPolygon('PGND') Or  IsNamedPolygon('D106_1') Or  IsNamedPolygon('PGND') Or  IsNamedPolygon('PGND') Or  IsNamedPolygon('D106_1') Or  IsNamedPolygon('VBB') Or  IsNamedPolygon('D106_1') Or  IsNamedPolygon('PGND')] p15: connectstyle=Direct reliefconductorwidth=0.254 reliefentries=4 polygonreliefangle="90 Angle" airgapwidth=0.254
PolygonConnect PolygonConnect_44 [All vs IsNamedPolygon('Earth1') Or  IsNamedPolygon('Vbulk1') Or  IsNamedPolygon('Vbulk1') Or  IsNamedPolygon('VBB') Or  IsNamedPolygon('Vbulk1') Or  IsNamedPolygon('ZCD') Or  IsNamedPolygon('VBB') Or  IsNamedPolygon('PGND') Or  IsNamedPolygon('C412_2') Or  IsNamedPolygon('ZCD') Or  IsNamedPolygon('D106_1') Or  IsNamedPolygon('D106_1') Or  IsNamedPolygon('ZCD') Or  IsNamedPolygon('PGND') Or  IsNamedPolygon('PGND') Or  IsNamedPolygon('ZCD') Or  IsNamedPolygon('VBB') Or  IsNamedPolygon('PGND') Or  IsNamedPolygon('VBB') Or  IsNamedPolygon('PGND') Or  IsNamedPolygon('D106_1') Or  IsNamedPolygon('PGND') Or  IsNamedPolygon('PGND') Or  IsNamedPolygon('PGND') Or  IsNamedPolygon('VBB') Or  IsNamedPolygon('PGND') Or  IsNamedPolygon('PGND') Or  IsNamedPolygon('C102_1') Or  IsNamedPolygon('ZCD') Or  IsNamedPolygon('C102_1') Or  IsNamedPolygon('C102_1') Or  IsNamedPolygon('C102_1') Or  IsNamedPolygon('PGND') Or  IsNamedPolygon('C102_1') Or  IsNamedPolygon('Line') Or  IsNamedPolygon('T200_4') Or  IsNamedPolygon('T200_4') Or  IsNamedPolygon('SIGNAL_LAYER_1_VBULK1_P106') Or  IsNamedPolygon('TOP_LAYER_VBULK_P104') Or  IsNamedPolygon('T200_4') Or  IsNamedPolygon('SGND') Or  IsNamedPolygon('T200_6') Or  IsNamedPolygon('C108_1') Or  IsNamedPolygon('SWNODE3') Or  IsNamedPolygon('SWNODE') Or  IsNamedPolygon('SWNODE3') Or  IsNamedPolygon('LEG3_HS_DRV') Or  IsNamedPolygon('BOTTOM_LAYER_NETC106_2_P030') Or  IsNamedPolygon('C102_1') Or  IsNamedPolygon('SWNODE4') Or  IsNamedPolygon('SIGNAL_LAYER_2_VBB_P094') Or  IsNamedPolygon('SGND') Or  IsNamedPolygon('VSR') Or  IsNamedPolygon('C108_1') Or  IsNamedPolygon('BOTTOM_LAYER_54V1_P128') Or  IsNamedPolygon('TOP_LAYER_54V2_P048') Or  IsNamedPolygon('TOP_LAYER_54V1_P046') Or  IsNamedPolygon('C108_1') Or  IsNamedPolygon('D403_2') Or  IsNamedPolygon('ZCD') Or  IsNamedPolygon('PGND') Or  IsNamedPolygon('SWNODE3') Or  IsNamedPolygon('Line') Or  IsNamedPolygon('D400_2') Or  IsNamedPolygon('SGND') Or  IsNamedPolygon('PGND') Or  IsNamedPolygon('SGND') Or  IsNamedPolygon('LEG4_HS_DRV') Or  IsNamedPolygon('SWNODE3') Or  IsNamedPolygon('5Vs') Or  IsNamedPolygon('SWNODE4') Or  IsNamedPolygon('SGND') Or  IsNamedPolygon('SGND') Or  IsNamedPolygon('C108_1') Or  IsNamedPolygon('5Vp') Or  IsNamedPolygon('12Vp') Or  IsNamedPolygon('Iout_SNS') Or  IsNamedPolygon('D404_2') Or  IsNamedPolygon('SGND') Or  IsNamedPolygon('T200_6') Or  IsNamedPolygon('TOP_LAYER_54V2_P048') Or  IsNamedPolygon('SGND') Or  IsNamedPolygon('SWNODE3') Or  IsNamedPolygon('SWNODE4') Or  IsNamedPolygon('Iout_SNS') Or  IsNamedPolygon('C108_1') Or  IsNamedPolygon('BOTTOM_LAYER_54V1_P128') Or  IsNamedPolygon('SWNODE3') Or  IsNamedPolygon('LEG4_LS_DRV') Or  IsNamedPolygon('SGND') Or  IsNamedPolygon('SWNODE4') Or  IsNamedPolygon('T200_6') Or  IsNamedPolygon('TOP_LAYER_12VS_P126') Or  IsNamedPolygon('Line') Or  IsNamedPolygon('Vbulk1') Or  IsNamedPolygon('SWNODE3') Or  IsNamedPolygon('SGND') Or  IsNamedPolygon('VBB') Or  IsNamedPolygon('SGND') Or  IsNamedPolygon('SGND') Or  IsNamedPolygon('SWNODE4') Or  IsNamedPolygon('PGND') Or  IsNamedPolygon('D403_2') Or  IsNamedPolygon('VSR') Or  IsNamedPolygon('SGND') Or  IsNamedPolygon('SGND') Or  IsNamedPolygon('VBB') Or  IsNamedPolygon('C108_1') Or  IsNamedPolygon('Earth1') Or  IsNamedPolygon('Earth1') Or  IsNamedPolygon('VSR') Or  IsNamedPolygon('C106_2') Or  IsNamedPolygon('Vbulk1') Or  IsNamedPolygon('C106_2') Or  IsNamedPolygon('C106_2') Or  IsNamedPolygon('Earth1') Or  IsNamedPolygon('SWNODE') Or  IsNamedPolygon('Neutral') Or  IsNamedPolygon('Earth1') Or  IsNamedPolygon('Earth1') Or  IsNamedPolygon('Neutral')] p16: connectstyle=Direct reliefconductorwidth=0.254 reliefentries=4 polygonreliefangle="90 Angle" airgapwidth=0.254
PolygonConnect PolygonConnect_43 [All vs IsNamedPolygon('SWNODE') Or  IsNamedPolygon('D403_2') Or  IsNamedPolygon('D403_2') Or  IsNamedPolygon('PGND') Or  IsNamedPolygon('BOTTOM_LAYER_NETC106_2_P030') Or  IsNamedPolygon('C102_1') Or  IsNamedPolygon('SGND') Or  IsNamedPolygon('TOP_LAYER_54V1_P046') Or  IsNamedPolygon('TOP_LAYER_54V2_P048') Or  IsNamedPolygon('TOP_LAYER_54V2_P048') Or  IsNamedPolygon('C108_1') Or  IsNamedPolygon('C108_1') Or  IsNamedPolygon('C108_1') Or  IsNamedPolygon('C108_1') Or  IsNamedPolygon('C108_1') Or  IsNamedPolygon('C108_1') Or  IsNamedPolygon('PGND') Or  IsNamedPolygon('ZCD') Or  IsNamedPolygon('Line') Or  IsNamedPolygon('5Vp') Or  IsNamedPolygon('12Vp') Or  IsNamedPolygon('T200_4') Or  IsNamedPolygon('T200_6') Or  IsNamedPolygon('SWNODE3') Or  IsNamedPolygon('T200_4') Or  IsNamedPolygon('T200_6') Or  IsNamedPolygon('SWNODE4') Or  IsNamedPolygon('VSR') Or  IsNamedPolygon('Iout_SNS') Or  IsNamedPolygon('SIGNAL_LAYER_2_VBB_P094') Or  IsNamedPolygon('Vbulk1') Or  IsNamedPolygon('TOP_LAYER_VBULK_P104') Or  IsNamedPolygon('SIGNAL_LAYER_1_VBULK1_P106') Or  IsNamedPolygon('Line') Or  IsNamedPolygon('Line') Or  IsNamedPolygon('D404_2') Or  IsNamedPolygon('VBB') Or  IsNamedPolygon('D400_2') Or  IsNamedPolygon('SGND') Or  IsNamedPolygon('PGND') Or  IsNamedPolygon('TOP_LAYER_12VS_P126') Or  IsNamedPolygon('BOTTOM_LAYER_54V1_P128') Or  IsNamedPolygon('LEG3_HS_DRV') Or  IsNamedPolygon('LEG4_LS_DRV') Or  IsNamedPolygon('LEG4_HS_DRV') Or  IsNamedPolygon('SWNODE4') Or  IsNamedPolygon('SWNODE3') Or  IsNamedPolygon('T200_6') Or  IsNamedPolygon('T200_4') Or  IsNamedPolygon('VBB') Or  IsNamedPolygon('5Vs') Or  IsNamedPolygon('SGND') Or  IsNamedPolygon('Iout_SNS') Or  IsNamedPolygon('SGND') Or  IsNamedPolygon('SWNODE3') Or  IsNamedPolygon('SWNODE3') Or  IsNamedPolygon('SWNODE3') Or  IsNamedPolygon('SWNODE3') Or  IsNamedPolygon('SGND') Or  IsNamedPolygon('SGND') Or  IsNamedPolygon('SGND') Or  IsNamedPolygon('SWNODE4') Or  IsNamedPolygon('SWNODE4') Or  IsNamedPolygon('SWNODE4') Or  IsNamedPolygon('VSR') Or  IsNamedPolygon('SWNODE3') Or  IsNamedPolygon('SGND') Or  IsNamedPolygon('SGND') Or  IsNamedPolygon('SGND') Or  IsNamedPolygon('SGND') Or  IsNamedPolygon('SGND') Or  IsNamedPolygon('SGND') Or  IsNamedPolygon('BOTTOM_LAYER_54V1_P128') Or  IsNamedPolygon('SGND') Or  IsNamedPolygon('VSR') Or  IsNamedPolygon('C102_1') Or  IsNamedPolygon('C102_1') Or  IsNamedPolygon('C102_1') Or  IsNamedPolygon('C102_1') Or  IsNamedPolygon('C102_1') Or  IsNamedPolygon('ZCD') Or  IsNamedPolygon('PGND') Or  IsNamedPolygon('PGND') Or  IsNamedPolygon('Vbulk1') Or  IsNamedPolygon('VBB') Or  IsNamedPolygon('Vbulk1') Or  IsNamedPolygon('Vbulk1') Or  IsNamedPolygon('ZCD') Or  IsNamedPolygon('Neutral') Or  IsNamedPolygon('Neutral') Or  IsNamedPolygon('C106_2') Or  IsNamedPolygon('C106_2') Or  IsNamedPolygon('C106_2') Or  IsNamedPolygon('SWNODE') Or  IsNamedPolygon('Vbulk1') Or  IsNamedPolygon('Earth1') Or  IsNamedPolygon('Earth1') Or  IsNamedPolygon('Earth1') Or  IsNamedPolygon('Earth1') Or  IsNamedPolygon('Earth1') Or  IsNamedPolygon('Earth1') Or  IsNamedPolygon('ZCD') Or  IsNamedPolygon('VBB') Or  IsNamedPolygon('PGND') Or  IsNamedPolygon('D106_1') Or  IsNamedPolygon('PGND') Or  IsNamedPolygon('PGND') Or  IsNamedPolygon('D106_1') Or  IsNamedPolygon('VBB') Or  IsNamedPolygon('D106_1') Or  IsNamedPolygon('PGND') Or  IsNamedPolygon('VBB') Or  IsNamedPolygon('VBB') Or  IsNamedPolygon('PGND') Or  IsNamedPolygon('PGND') Or  IsNamedPolygon('PGND') Or  IsNamedPolygon('PGND') Or  IsNamedPolygon('PGND')] p17: connectstyle=Direct reliefconductorwidth=0.254 reliefentries=4 polygonreliefangle="90 Angle" airgapwidth=0.254
PolygonConnect PolygonConnect_42 [All vs IsNamedPolygon('Neutral') Or  IsNamedPolygon('Earth1') Or  IsNamedPolygon('Earth1') Or  IsNamedPolygon('D404_2') Or  IsNamedPolygon('Line') Or  IsNamedPolygon('SIGNAL_LAYER_1_VBULK1_P106') Or  IsNamedPolygon('Line') Or  IsNamedPolygon('C102_1') Or  IsNamedPolygon('SWNODE3') Or  IsNamedPolygon('SWNODE3') Or  IsNamedPolygon('SWNODE') Or  IsNamedPolygon('5Vp') Or  IsNamedPolygon('T200_6') Or  IsNamedPolygon('SWNODE3') Or  IsNamedPolygon('SGND') Or  IsNamedPolygon('SWNODE3') Or  IsNamedPolygon('VSR') Or  IsNamedPolygon('C108_1') Or  IsNamedPolygon('SWNODE3') Or  IsNamedPolygon('TOP_LAYER_12VS_P126') Or  IsNamedPolygon('SGND') Or  IsNamedPolygon('SGND') Or  IsNamedPolygon('SGND') Or  IsNamedPolygon('T200_6') Or  IsNamedPolygon('SWNODE4') Or  IsNamedPolygon('C108_1') Or  IsNamedPolygon('C106_2') Or  IsNamedPolygon('SGND') Or  IsNamedPolygon('Neutral') Or  IsNamedPolygon('SIGNAL_LAYER_2_VBB_P094') Or  IsNamedPolygon('Vbulk1') Or  IsNamedPolygon('SGND') Or  IsNamedPolygon('SGND') Or  IsNamedPolygon('TOP_LAYER_54V1_P046') Or  IsNamedPolygon('TOP_LAYER_54V2_P048') Or  IsNamedPolygon('TOP_LAYER_54V2_P048') Or  IsNamedPolygon('C102_1') Or  IsNamedPolygon('SGND') Or  IsNamedPolygon('T200_4') Or  IsNamedPolygon('12Vp') Or  IsNamedPolygon('SGND') Or  IsNamedPolygon('D400_2') Or  IsNamedPolygon('LEG3_HS_DRV') Or  IsNamedPolygon('LEG4_LS_DRV') Or  IsNamedPolygon('T200_4') Or  IsNamedPolygon('BOTTOM_LAYER_54V1_P128') Or  IsNamedPolygon('SGND') Or  IsNamedPolygon('VBB') Or  IsNamedPolygon('SWNODE4') Or  IsNamedPolygon('SWNODE4') Or  IsNamedPolygon('SWNODE4') Or  IsNamedPolygon('VSR') Or  IsNamedPolygon('Iout_SNS') Or  IsNamedPolygon('VBB') Or  IsNamedPolygon('PGND') Or  IsNamedPolygon('Line') Or  IsNamedPolygon('ZCD') Or  IsNamedPolygon('D403_2') Or  IsNamedPolygon('SWNODE3') Or  IsNamedPolygon('Vbulk1') Or  IsNamedPolygon('ZCD') Or  IsNamedPolygon('LEG4_HS_DRV') Or  IsNamedPolygon('BOTTOM_LAYER_54V1_P128') Or  IsNamedPolygon('VBB') Or  IsNamedPolygon('PGND') Or  IsNamedPolygon('ZCD') Or  IsNamedPolygon('ZCD') Or  IsNamedPolygon('Earth1') Or  IsNamedPolygon('VBB') Or  IsNamedPolygon('PGND') Or  IsNamedPolygon('PGND') Or  IsNamedPolygon('Vbulk1') Or  IsNamedPolygon('SWNODE') Or  IsNamedPolygon('C106_2') Or  IsNamedPolygon('C106_2') Or  IsNamedPolygon('C108_1') Or  IsNamedPolygon('SWNODE3') Or  IsNamedPolygon('SWNODE4') Or  IsNamedPolygon('Vbulk1') Or  IsNamedPolygon('SGND') Or  IsNamedPolygon('C102_1') Or  IsNamedPolygon('BOTTOM_LAYER_NETC106_2_P030') Or  IsNamedPolygon('Earth1') Or  IsNamedPolygon('Earth1') Or  IsNamedPolygon('Vbulk1') Or  IsNamedPolygon('Earth1') Or  IsNamedPolygon('T200_6') Or  IsNamedPolygon('T200_4') Or  IsNamedPolygon('C102_1') Or  IsNamedPolygon('C102_1') Or  IsNamedPolygon('C102_1') Or  IsNamedPolygon('VBB') Or  IsNamedPolygon('5Vs') Or  IsNamedPolygon('SGND') Or  IsNamedPolygon('Iout_SNS') Or  IsNamedPolygon('C108_1') Or  IsNamedPolygon('C108_1') Or  IsNamedPolygon('C108_1') Or  IsNamedPolygon('PGND') Or  IsNamedPolygon('D403_2') Or  IsNamedPolygon('PGND') Or  IsNamedPolygon('SGND') Or  IsNamedPolygon('SGND') Or  IsNamedPolygon('VSR')] p18: connectstyle=Direct reliefconductorwidth=0.254 reliefentries=4 polygonreliefangle="90 Angle" airgapwidth=0.254
PolygonConnect PolygonConnect_41 [All vs IsNamedPolygon('VBB') Or  IsNamedPolygon('SWNODE3') Or  IsNamedPolygon('T200_4') Or  IsNamedPolygon('Earth1') Or  IsNamedPolygon('BOTTOM_LAYER_54V1_P128') Or  IsNamedPolygon('SGND') Or  IsNamedPolygon('TOP_LAYER_12VS_P126') Or  IsNamedPolygon('C102_1') Or  IsNamedPolygon('VSR') Or  IsNamedPolygon('Earth1') Or  IsNamedPolygon('Neutral') Or  IsNamedPolygon('Vbulk1') Or  IsNamedPolygon('SWNODE4') Or  IsNamedPolygon('C106_2') Or  IsNamedPolygon('PGND') Or  IsNamedPolygon('SGND') Or  IsNamedPolygon('VBB') Or  IsNamedPolygon('PGND') Or  IsNamedPolygon('LEG4_LS_DRV') Or  IsNamedPolygon('C102_1') Or  IsNamedPolygon('SWNODE4') Or  IsNamedPolygon('C106_2') Or  IsNamedPolygon('Vbulk1') Or  IsNamedPolygon('C102_1') Or  IsNamedPolygon('BOTTOM_LAYER_54V1_P128') Or  IsNamedPolygon('LEG3_HS_DRV') Or  IsNamedPolygon('SGND') Or  IsNamedPolygon('SGND') Or  IsNamedPolygon('Earth1') Or  IsNamedPolygon('SGND') Or  IsNamedPolygon('SGND') Or  IsNamedPolygon('5Vs') Or  IsNamedPolygon('LEG4_HS_DRV') Or  IsNamedPolygon('Earth1') Or  IsNamedPolygon('SGND') Or  IsNamedPolygon('SWNODE3') Or  IsNamedPolygon('Iout_SNS') Or  IsNamedPolygon('ZCD') Or  IsNamedPolygon('Earth1') Or  IsNamedPolygon('VSR') Or  IsNamedPolygon('C102_1') Or  IsNamedPolygon('C102_1') Or  IsNamedPolygon('Vbulk1') Or  IsNamedPolygon('C106_2') Or  IsNamedPolygon('ZCD') Or  IsNamedPolygon('SWNODE3') Or  IsNamedPolygon('SWNODE3') Or  IsNamedPolygon('Vbulk1') Or  IsNamedPolygon('SWNODE4') Or  IsNamedPolygon('Neutral') Or  IsNamedPolygon('SWNODE3') Or  IsNamedPolygon('SWNODE4') Or  IsNamedPolygon('Earth1') Or  IsNamedPolygon('D400_2') Or  IsNamedPolygon('SGND') Or  IsNamedPolygon('SGND') Or  IsNamedPolygon('SGND') Or  IsNamedPolygon('SWNODE') Or  IsNamedPolygon('VSR') Or  IsNamedPolygon('SGND') Or  IsNamedPolygon('SIGNAL_LAYER_1_VBULK1_P106') Or  IsNamedPolygon('SGND') Or  IsNamedPolygon('T200_6') Or  IsNamedPolygon('SWNODE4') Or  IsNamedPolygon('VBB') Or  IsNamedPolygon('T200_6') Or  IsNamedPolygon('Line') Or  IsNamedPolygon('Iout_SNS') Or  IsNamedPolygon('Vbulk1') Or  IsNamedPolygon('VBB') Or  IsNamedPolygon('SIGNAL_LAYER_2_VBB_P094') Or  IsNamedPolygon('SGND') Or  IsNamedPolygon('D404_2') Or  IsNamedPolygon('SWNODE3') Or  IsNamedPolygon('Line') Or  IsNamedPolygon('PGND') Or  IsNamedPolygon('TOP_LAYER_54V2_P048') Or  IsNamedPolygon('TOP_LAYER_54V1_P046') Or  IsNamedPolygon('TOP_LAYER_54V2_P048') Or  IsNamedPolygon('C108_1') Or  IsNamedPolygon('BOTTOM_LAYER_NETC106_2_P030') Or  IsNamedPolygon('D403_2') Or  IsNamedPolygon('T200_4') Or  IsNamedPolygon('Line') Or  IsNamedPolygon('PGND') Or  IsNamedPolygon('SWNODE3') Or  IsNamedPolygon('ZCD') Or  IsNamedPolygon('SWNODE') Or  IsNamedPolygon('D403_2') Or  IsNamedPolygon('C108_1') Or  IsNamedPolygon('C102_1') Or  IsNamedPolygon('C108_1') Or  IsNamedPolygon('PGND') Or  IsNamedPolygon('C108_1') Or  IsNamedPolygon('C108_1') Or  IsNamedPolygon('5Vp') Or  IsNamedPolygon('T200_4') Or  IsNamedPolygon('12Vp') Or  IsNamedPolygon('T200_6') Or  IsNamedPolygon('C108_1') Or  IsNamedPolygon('SGND')] p19: connectstyle=Direct reliefconductorwidth=0.254 reliefentries=4 polygonreliefangle="90 Angle" airgapwidth=0.254
PolygonConnect PolygonConnect_40 [All vs IsNamedPolygon('Neutral')] p20: connectstyle=Direct reliefconductorwidth=0.254 reliefentries=4 polygonreliefangle="90 Angle" airgapwidth=0.254
PolygonConnect PolygonConnect_39 [All vs IsNamedPolygon('12Vp')] p21: connectstyle=Direct reliefconductorwidth=0.254 reliefentries=4 polygonreliefangle="90 Angle" airgapwidth=0.254
PolygonConnect PolygonConnect_38 [All vs IsNamedPolygon('SWNODE') Or  IsNamedPolygon('D403_2') Or  IsNamedPolygon('D403_2') Or  IsNamedPolygon('PGND') Or  IsNamedPolygon('BOTTOM_LAYER_NETC106_2_P030') Or  IsNamedPolygon('C102_1') Or  IsNamedPolygon('SGND') Or  IsNamedPolygon('TOP_LAYER_54V1_P046') Or  IsNamedPolygon('TOP_LAYER_54V2_P048') Or  IsNamedPolygon('TOP_LAYER_54V2_P048') Or  IsNamedPolygon('C108_1') Or  IsNamedPolygon('C108_1') Or  IsNamedPolygon('C108_1') Or  IsNamedPolygon('C108_1') Or  IsNamedPolygon('C108_1') Or  IsNamedPolygon('C108_1') Or  IsNamedPolygon('PGND') Or  IsNamedPolygon('ZCD') Or  IsNamedPolygon('Line') Or  IsNamedPolygon('5Vp') Or  IsNamedPolygon('12Vp') Or  IsNamedPolygon('T200_4') Or  IsNamedPolygon('T200_6') Or  IsNamedPolygon('SWNODE3') Or  IsNamedPolygon('T200_4') Or  IsNamedPolygon('T200_6') Or  IsNamedPolygon('SWNODE4') Or  IsNamedPolygon('VSR') Or  IsNamedPolygon('Iout_SNS') Or  IsNamedPolygon('SIGNAL_LAYER_2_VBB_P094') Or  IsNamedPolygon('Vbulk1') Or  IsNamedPolygon('VBB') Or  IsNamedPolygon('SIGNAL_LAYER_1_VBULK1_P106') Or  IsNamedPolygon('Line') Or  IsNamedPolygon('Line') Or  IsNamedPolygon('Line') Or  IsNamedPolygon('D404_2') Or  IsNamedPolygon('VBB') Or  IsNamedPolygon('D400_2') Or  IsNamedPolygon('SGND') Or  IsNamedPolygon('PGND') Or  IsNamedPolygon('TOP_LAYER_12VS_P126') Or  IsNamedPolygon('BOTTOM_LAYER_54V1_P128') Or  IsNamedPolygon('LEG3_HS_DRV') Or  IsNamedPolygon('LEG4_LS_DRV') Or  IsNamedPolygon('LEG4_HS_DRV') Or  IsNamedPolygon('SWNODE4') Or  IsNamedPolygon('SWNODE3') Or  IsNamedPolygon('T200_6') Or  IsNamedPolygon('T200_4') Or  IsNamedPolygon('VBB') Or  IsNamedPolygon('5Vs') Or  IsNamedPolygon('SGND') Or  IsNamedPolygon('Iout_SNS') Or  IsNamedPolygon('SGND') Or  IsNamedPolygon('SWNODE3') Or  IsNamedPolygon('SWNODE3') Or  IsNamedPolygon('SWNODE3') Or  IsNamedPolygon('SWNODE3') Or  IsNamedPolygon('SGND') Or  IsNamedPolygon('SGND') Or  IsNamedPolygon('SGND') Or  IsNamedPolygon('SWNODE4') Or  IsNamedPolygon('SWNODE4') Or  IsNamedPolygon('SWNODE4') Or  IsNamedPolygon('VSR') Or  IsNamedPolygon('SWNODE3') Or  IsNamedPolygon('SGND') Or  IsNamedPolygon('SGND') Or  IsNamedPolygon('SGND') Or  IsNamedPolygon('SGND') Or  IsNamedPolygon('SGND') Or  IsNamedPolygon('SGND') Or  IsNamedPolygon('BOTTOM_LAYER_54V1_P128') Or  IsNamedPolygon('SGND') Or  IsNamedPolygon('VSR') Or  IsNamedPolygon('C102_1') Or  IsNamedPolygon('C102_1') Or  IsNamedPolygon('C102_1') Or  IsNamedPolygon('C102_1') Or  IsNamedPolygon('C102_1') Or  IsNamedPolygon('ZCD') Or  IsNamedPolygon('PGND') Or  IsNamedPolygon('PGND') Or  IsNamedPolygon('Vbulk1') Or  IsNamedPolygon('VBB') Or  IsNamedPolygon('Vbulk1') Or  IsNamedPolygon('Vbulk1') Or  IsNamedPolygon('ZCD') Or  IsNamedPolygon('Neutral') Or  IsNamedPolygon('Neutral')] p22: connectstyle=Direct reliefconductorwidth=0.254 reliefentries=4 polygonreliefangle="90 Angle" airgapwidth=0.254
